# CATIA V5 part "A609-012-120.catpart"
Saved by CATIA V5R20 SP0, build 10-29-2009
Part number: A609-012-120
Source: Unknown
Property "ARTICLENO": "A609-012-120"
Property "B": "12.500"
Property "BOMINFO": "A609-012-120"
Property "CODE": "A609-012-120"
Property "D": "15.000"
Property "D1": "9.000"
Property "FORM": "A"
Property "L": "120.000"
Property "L1": "25.000"
Property "L2": "70.000"
Property "LINA": "A609-012-120"
Property "NB": "A609-012-120"
Property "NBSYN": "$CODE."
Property "NN": "A609"
Property "NT": "VDI 3357 E-Type Wear Plates, self-lubricating"
Property "S": "12.000"
Property "SUPPLIER": "CF"
Property "T": "8.500"
Property "W": "25.000"
Bounding box of the stored display mesh (mm): x 0 to 120, y 0 to 12, z 0 to 25
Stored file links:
  C:\Users\Utente\Desktop\3D files A609\A609-012-120.catpart
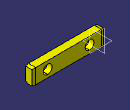
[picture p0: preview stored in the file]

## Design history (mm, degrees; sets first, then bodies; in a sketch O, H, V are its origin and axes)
Body1 "Geometry.1" (main body)
  Solid1 "A609-012-120.catpart": solid without history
